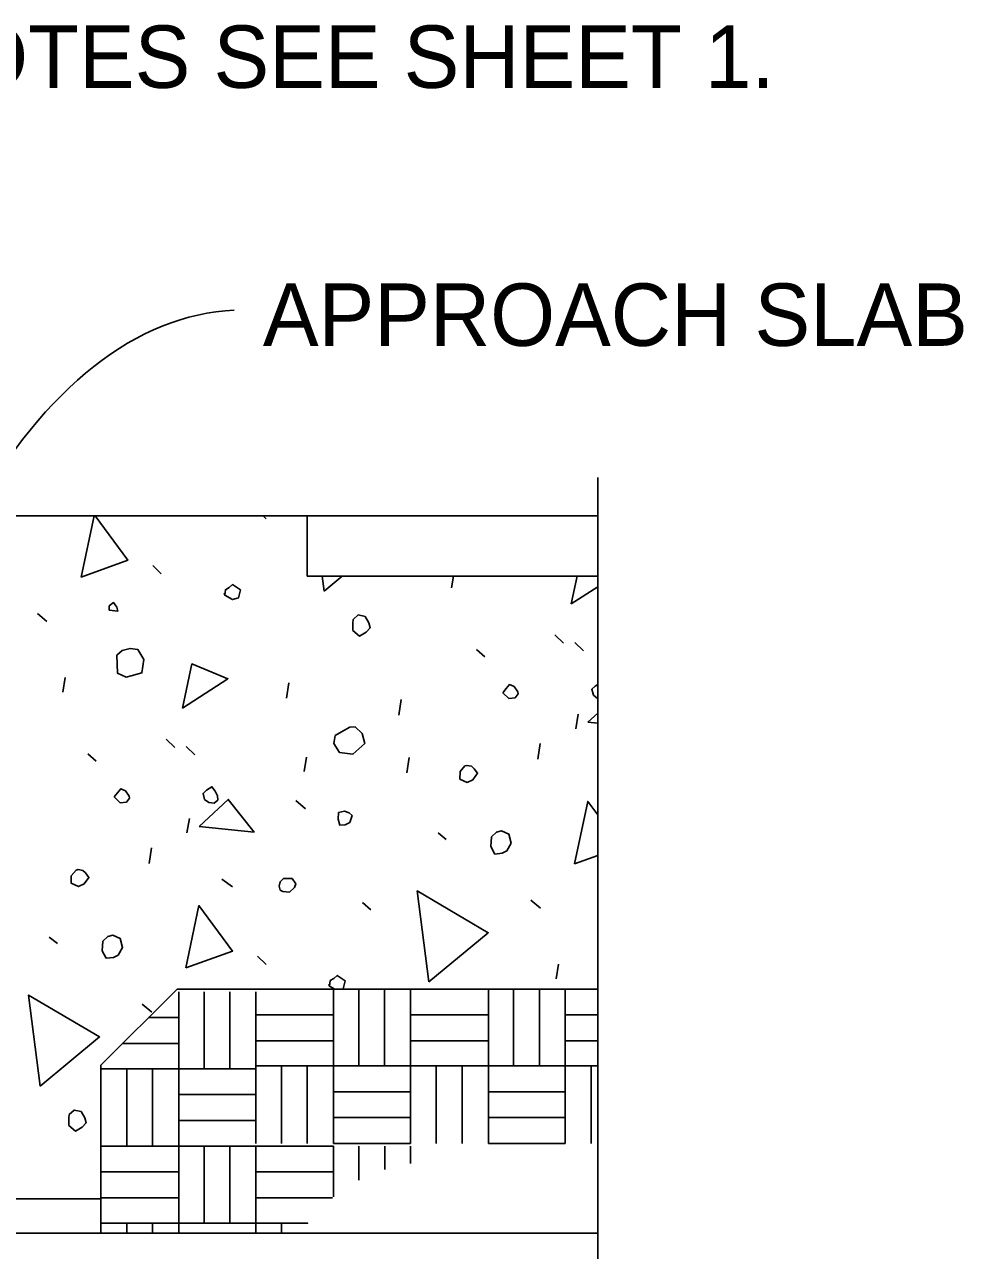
# Model space of a CAD drawing. Extents: x -1660015.2 to -1659984.9, y 2580594.2 to 2580616.7.
# Drawn here: x -1659987.657 to -1659985.382, y 2580602.277 to 2580605.246 of the extents above; entities that cross this region are included whole.
import ezdxf

# ---------------------------------------------------------------- set-up
doc = ezdxf.new("R2010")
doc.units = 0
for name, color, linetype in [('Default', 7, 'Continuous'), ('Miscellaneous', 7, 'Continuous'), ('Miscellaneous3', 7, 'Continuous'), ('PlotBorder_dp', 7, 'Continuous'), ('SheetLines_dp', 7, 'Continuous')]:
    doc.layers.add(name, color=color, linetype=linetype)

msp = doc.modelspace()

# ---------------------------------------------------------------- linework, layer by layer
at = {"layer": 'Default'}
msp.add_line((-1659986.2685, 2580602.3187), (-1659989.3273, 2580602.3187), dxfattribs=at)
at = {"layer": 'Miscellaneous'}
for p, q in [((-1659987.0793, 2580604.056), (-1659987.0714, 2580604.049)), ((-1659986.2685, 2580604.056), (-1659986.972, 2580604.056)), ((-1659987.3466, 2580603.9364), (-1659987.3257, 2580603.9161)), ((-1659986.6228, 2580603.8819), (-1659986.618, 2580603.9102)), ((-1659987.626, 2580603.8201), (-1659987.6027, 2580603.8005)), ((-1659986.3723, 2580603.7678), (-1659986.3513, 2580603.7476)), ((-1659986.5621, 2580603.7325), (-1659986.5418, 2580603.7146)), ((-1659986.3235, 2580603.7498), (-1659986.3025, 2580603.7296)), ((-1659987.5646, 2580603.6295), (-1659987.5585, 2580603.6648)), ((-1659987.0222, 2580603.6144), (-1659987.0168, 2580603.6521)), ((-1659986.7499, 2580603.5735), (-1659986.7444, 2580603.6112)), ((-1659986.3218, 2580603.5407), (-1659986.3157, 2580603.5759)), ((-1659987.3141, 2580603.5155), (-1659987.2931, 2580603.4952)), ((-1659987.2653, 2580603.4975), (-1659987.2443, 2580603.4772)), ((-1659986.4133, 2580603.4669), (-1659986.4079, 2580603.5046)), ((-1659987.5039, 2580603.4801), (-1659987.4836, 2580603.4623)), ((-1659986.9798, 2580603.4368), (-1659986.9737, 2580603.4721)), ((-1659986.7305, 2580603.4337), (-1659986.7251, 2580603.4714)), ((-1659986.9999, 2580603.3667), (-1659986.9765, 2580603.3471)), ((-1659987.2636, 2580603.2883), (-1659987.2575, 2580603.3236)), ((-1659986.6553, 2580603.2882), (-1659986.6356, 2580603.2728)), ((-1659987.3551, 2580603.2146), (-1659987.3497, 2580603.2523)), ((-1659987.1792, 2580603.1763), (-1659987.1534, 2580603.1574)), ((-1659986.838, 2580603.1202), (-1659986.8177, 2580603.1024)), ((-1659986.4306, 2580603.1258), (-1659986.4073, 2580603.1062)), ((-1659987.5971, 2580603.0359), (-1659987.5774, 2580603.0204)), ((-1659987.093, 2580602.9898), (-1659987.072, 2580602.9695)), ((-1659986.3692, 2580602.9352), (-1659986.3631, 2580602.9705)), ((-1659987.2832, 2580602.5297), (-1659987.2832, 2580602.9035)), ((-1659987.2219, 2580602.7172), (-1659987.2219, 2580602.9035)), ((-1659987.1594, 2580602.7172), (-1659987.1594, 2580602.9035)), ((-1659987.0971, 2580602.9101), (-1659986.9083, 2580602.9101)), ((-1659987.0969, 2580602.7172), (-1659987.0969, 2580602.9035)), ((-1659986.9083, 2580602.5364), (-1659986.9083, 2580602.9101)), ((-1659986.8471, 2580602.7239), (-1659986.8471, 2580602.9101)), ((-1659986.7846, 2580602.7239), (-1659986.7846, 2580602.9101)), ((-1659986.7221, 2580602.9101), (-1659986.5333, 2580602.9101)), ((-1659986.7221, 2580602.7239), (-1659986.7221, 2580602.9101)), ((-1659986.5333, 2580602.5364), (-1659986.5333, 2580602.9101)), ((-1659986.4721, 2580602.7239), (-1659986.4721, 2580602.9101)), ((-1659986.4096, 2580602.7239), (-1659986.4096, 2580602.9101)), ((-1659986.3471, 2580602.7239), (-1659986.3471, 2580602.9101)), ((-1659987.3724, 2580602.8735), (-1659987.349, 2580602.8539)), ((-1659987.3564, 2580602.841), (-1659987.2832, 2580602.841)), ((-1659987.0971, 2580602.8476), (-1659986.9083, 2580602.8476)), ((-1659986.7221, 2580602.8476), (-1659986.5333, 2580602.8476)), ((-1659986.3471, 2580602.8477), (-1659986.2685, 2580602.8477)), ((-1659987.0971, 2580602.7851), (-1659986.9083, 2580602.7851)), ((-1659986.7221, 2580602.7851), (-1659986.5333, 2580602.7851)), ((-1659986.3471, 2580602.7852), (-1659986.2685, 2580602.7852)), ((-1659987.4189, 2580602.7785), (-1659987.2832, 2580602.7785)), ((-1659987.0971, 2580602.7239), (-1659986.7221, 2580602.7239)), ((-1659987.0971, 2580602.7239), (-1659987.0971, 2580602.5364)), ((-1659987.0346, 2580602.7239), (-1659987.0346, 2580602.5364)), ((-1659986.9721, 2580602.7239), (-1659986.9721, 2580602.5364)), ((-1659986.7221, 2580602.7239), (-1659986.3471, 2580602.7239)), ((-1659986.7221, 2580602.7239), (-1659986.7221, 2580602.5364)), ((-1659986.6596, 2580602.7239), (-1659986.6596, 2580602.5364)), ((-1659986.5971, 2580602.7239), (-1659986.5971, 2580602.5364)), ((-1659986.3471, 2580602.7239), (-1659986.2685, 2580602.7239)), ((-1659986.3471, 2580602.7239), (-1659986.3471, 2580602.5364)), ((-1659986.2846, 2580602.7239), (-1659986.2846, 2580602.5364)), ((-1659987.4719, 2580602.7172), (-1659987.0969, 2580602.7172)), ((-1659987.4094, 2580602.7172), (-1659987.4094, 2580602.5297)), ((-1659987.3469, 2580602.7172), (-1659987.3469, 2580602.5297)), ((-1659987.2832, 2580602.6547), (-1659987.0969, 2580602.6547)), ((-1659986.9083, 2580602.6614), (-1659986.7221, 2580602.6614)), ((-1659986.5333, 2580602.6614), (-1659986.3471, 2580602.6614)), ((-1659987.2832, 2580602.5922), (-1659987.0969, 2580602.5922)), ((-1659986.9083, 2580602.5989), (-1659986.7221, 2580602.5989)), ((-1659986.5333, 2580602.5989), (-1659986.3471, 2580602.5989)), ((-1659987.4719, 2580602.5297), (-1659987.2832, 2580602.5297)), ((-1659987.2832, 2580602.3187), (-1659987.2832, 2580602.5298)), ((-1659987.2832, 2580602.5297), (-1659987.0969, 2580602.5297)), ((-1659987.2219, 2580602.3435), (-1659987.2219, 2580602.5297)), ((-1659987.1594, 2580602.3435), (-1659987.1594, 2580602.5297)), ((-1659987.0969, 2580602.5297), (-1659986.9082, 2580602.5297)), ((-1659987.0969, 2580602.3435), (-1659987.0969, 2580602.5297)), ((-1659986.9083, 2580602.5364), (-1659986.7221, 2580602.5364)), ((-1659986.9082, 2580602.4069), (-1659986.9082, 2580602.5298)), ((-1659986.8469, 2580602.447), (-1659986.8469, 2580602.5298)), ((-1659986.7844, 2580602.4735), (-1659986.7844, 2580602.5298)), ((-1659986.7219, 2580602.4875), (-1659986.7219, 2580602.5298)), ((-1659986.5333, 2580602.5364), (-1659986.3471, 2580602.5364)), ((-1659987.4719, 2580602.4672), (-1659987.2832, 2580602.4672)), ((-1659987.0969, 2580602.4672), (-1659986.9082, 2580602.4672)), ((-1659987.472, 2580602.402), (-1659988.972, 2580602.402)), ((-1659987.4719, 2580602.4047), (-1659987.2832, 2580602.4047)), ((-1659987.0969, 2580602.4048), (-1659986.9108, 2580602.4048)), ((-1659987.4719, 2580602.3435), (-1659987.0969, 2580602.3435)), ((-1659987.4094, 2580602.3435), (-1659987.4094, 2580602.3187)), ((-1659987.3469, 2580602.3435), (-1659987.3469, 2580602.3187)), ((-1659987.0969, 2580602.3435), (-1659986.9711, 2580602.3435)), ((-1659987.0969, 2580602.3435), (-1659987.0969, 2580602.3187)), ((-1659987.0344, 2580602.3435), (-1659987.0344, 2580602.3187)), ((-1659986.9719, 2580602.3435), (-1659986.9719, 2580602.3425))]:
    msp.add_line(p, q, dxfattribs=at)
for points in [[(-1659987.5202, 2580603.908), (-1659987.4888, 2580604.056)], [(-1659987.486, 2580604.056), (-1659987.4069, 2580603.9487), (-1659987.5202, 2580603.908)], [(-1659986.9314, 2580603.8742), (-1659986.9359, 2580603.9102)], [(-1659986.8878, 2580603.9102), (-1659986.9314, 2580603.8742)], [(-1659986.3329, 2580603.8431), (-1659986.3185, 2580603.9102)], [(-1659987.172, 2580603.8641), (-1659987.1536, 2580603.8535), (-1659987.1391, 2580603.8574), (-1659987.134, 2580603.8769), (-1659987.153, 2580603.8899), (-1659987.1614, 2580603.8825), (-1659987.1704, 2580603.8775), (-1659987.172, 2580603.8641), (-1659987.1733, 2580603.869)], [(-1659986.2685, 2580603.8845), (-1659986.3329, 2580603.8431)], [(-1659987.4521, 2580603.8279), (-1659987.4309, 2580603.8258), (-1659987.4335, 2580603.8355), (-1659987.4415, 2580603.8463), (-1659987.4523, 2580603.8382), (-1659987.4521, 2580603.8279)], [(-1659986.8616, 2580603.7972), (-1659986.8619, 2580603.779), (-1659986.8453, 2580603.7653), (-1659986.8297, 2580603.7747), (-1659986.8195, 2580603.7852), (-1659986.8228, 2580603.7972), (-1659986.8321, 2580603.8128), (-1659986.8485, 2580603.8162), (-1659986.8611, 2580603.8051), (-1659986.8616, 2580603.7972)], [(-1659987.4333, 2580603.719), (-1659987.432, 2580603.6754), (-1659987.4112, 2580603.6654), (-1659987.3991, 2580603.6687), (-1659987.3726, 2580603.6758), (-1659987.3682, 2580603.708), (-1659987.3826, 2580603.7326), (-1659987.4015, 2580603.7353), (-1659987.4208, 2580603.7302), (-1659987.4333, 2580603.719)], [(-1659987.2747, 2580603.5907), (-1659987.2516, 2580603.6978), (-1659987.1643, 2580603.6617), (-1659987.2747, 2580603.5907)], [(-1659986.4979, 2580603.628), (-1659986.4837, 2580603.6137), (-1659986.4686, 2580603.6152), (-1659986.4609, 2580603.625), (-1659986.4621, 2580603.6299), (-1659986.4709, 2580603.6431), (-1659986.4825, 2580603.6477), (-1659986.4902, 2580603.6379), (-1659986.4979, 2580603.628)], [(-1659986.2685, 2580603.6479), (-1659986.2744, 2580603.6439), (-1659986.2828, 2580603.6365), (-1659986.2789, 2580603.622)], [(-1659986.2789, 2580603.622), (-1659986.269, 2580603.6143), (-1659986.2685, 2580603.6142)], [(-1659986.2923, 2580603.5563), (-1659986.2685, 2580603.5785)], [(-1659986.2685, 2580603.5539), (-1659986.2923, 2580603.5563)], [(-1659986.9076, 2580603.5053), (-1659986.8939, 2580603.4831), (-1659986.8617, 2580603.4788), (-1659986.8324, 2580603.5048), (-1659986.8389, 2580603.5289), (-1659986.8561, 2580603.545), (-1659986.8688, 2580603.5442), (-1659986.8893, 2580603.5335), (-1659986.9049, 2580603.5242), (-1659986.9076, 2580603.5053)], [(-1659986.602, 2580603.4371), (-1659986.6023, 2580603.4189), (-1659986.5846, 2580603.4107), (-1659986.5708, 2580603.417), (-1659986.5595, 2580603.433), (-1659986.5676, 2580603.4437), (-1659986.5743, 2580603.4497), (-1659986.5853, 2580603.4519), (-1659986.5901, 2580603.4506), (-1659986.602, 2580603.4371)], [(-1659987.4397, 2580603.3757), (-1659987.4255, 2580603.3614), (-1659987.4103, 2580603.3629), (-1659987.4026, 2580603.3727), (-1659987.4039, 2580603.3775), (-1659987.4126, 2580603.3907), (-1659987.4242, 2580603.3954), (-1659987.432, 2580603.3855), (-1659987.4397, 2580603.3757)], [(-1659987.2207, 2580603.3697), (-1659987.2108, 2580603.362), (-1659987.1975, 2580603.3604), (-1659987.1891, 2580603.3678), (-1659987.1893, 2580603.3781), (-1659987.1949, 2580603.3895), (-1659987.203, 2580603.4003), (-1659987.2162, 2580603.3916), (-1659987.2245, 2580603.3842), (-1659987.2207, 2580603.3697)], [(-1659987.2341, 2580603.304), (-1659987.1636, 2580603.3694), (-1659987.1011, 2580603.2904), (-1659987.2341, 2580603.304)], [(-1659986.3248, 2580603.2137), (-1659986.2927, 2580603.3647), (-1659986.2685, 2580603.3318)], [(-1659986.8972, 2580603.3218), (-1659986.8933, 2580603.3073), (-1659986.8806, 2580603.3081), (-1659986.8692, 2580603.3137), (-1659986.8634, 2580603.3308), (-1659986.8702, 2580603.3368), (-1659986.8818, 2580603.3414), (-1659986.8963, 2580603.3375), (-1659986.8972, 2580603.3218)], [(-1659986.526, 2580603.2789), (-1659986.5274, 2580603.2552), (-1659986.5174, 2580603.2372), (-1659986.4998, 2580603.2393), (-1659986.4884, 2580603.2449), (-1659986.4778, 2580603.2633), (-1659986.4836, 2580603.2851), (-1659986.5014, 2580603.2932), (-1659986.5134, 2580603.29), (-1659986.526, 2580603.2789)], [(-1659986.2685, 2580603.234), (-1659986.3248, 2580603.2137)], [(-1659987.5438, 2580603.1847), (-1659987.5441, 2580603.1665), (-1659987.5264, 2580603.1584), (-1659987.5125, 2580603.1647), (-1659987.5013, 2580603.1806), (-1659987.5093, 2580603.1914), (-1659987.5161, 2580603.1973), (-1659987.5271, 2580603.1996), (-1659987.5319, 2580603.1983), (-1659987.5438, 2580603.1847)], [(-1659987.0374, 2580603.1496), (-1659987.0313, 2580603.1461), (-1659987.0155, 2580603.1451), (-1659987.003, 2580603.1562), (-1659987.0001, 2580603.1648), (-1659987.0088, 2580603.178), (-1659987.0294, 2580603.1776), (-1659987.0378, 2580603.1702), (-1659987.04, 2580603.1593), (-1659987.0374, 2580603.1496)], [(-1659986.6777, 2580602.9276), (-1659986.7057, 2580603.1479), (-1659986.5336, 2580603.0465), (-1659986.6777, 2580602.9276)], [(-1659987.2665, 2580602.9614), (-1659987.2345, 2580603.1123), (-1659987.1532, 2580603.0021), (-1659987.2665, 2580602.9614)], [(-1659987.4678, 2580603.0265), (-1659987.4692, 2580603.0029), (-1659987.4592, 2580602.9848), (-1659987.4416, 2580602.9869), (-1659987.4302, 2580602.9926), (-1659987.4196, 2580603.011), (-1659987.4254, 2580603.0327), (-1659987.4431, 2580603.0409), (-1659987.4552, 2580603.0377), (-1659987.4678, 2580603.0265)], [(-1659986.8878, 2580602.9102), (-1659986.8855, 2580602.9108), (-1659986.8803, 2580602.9303), (-1659986.8994, 2580602.9433), (-1659986.9077, 2580602.9359), (-1659986.9167, 2580602.9309), (-1659986.9183, 2580602.9175), (-1659986.9196, 2580602.9224)], [(-1659986.9183, 2580602.9175), (-1659986.9056, 2580602.9102)], [(-1659987.6195, 2580602.6753), (-1659987.6475, 2580602.8956), (-1659987.4754, 2580602.7941), (-1659987.6195, 2580602.6753)], [(-1659987.5497, 2580602.5982), (-1659987.55, 2580602.58), (-1659987.5334, 2580602.5664), (-1659987.5178, 2580602.5757), (-1659987.5077, 2580602.5862), (-1659987.5109, 2580602.5983), (-1659987.5202, 2580602.6139), (-1659987.5367, 2580602.6172), (-1659987.5492, 2580602.6061), (-1659987.5497, 2580602.5982)]]:
    msp.add_lwpolyline(points, dxfattribs=at)
at = {"layer": 'Miscellaneous3'}
for p, q in [((-1659986.972, 2580604.056), (-1659988.972, 2580604.056)), ((-1659986.972, 2580604.056), (-1659986.972, 2580603.9102)), ((-1659986.2685, 2580603.9102), (-1659986.972, 2580603.9102)), ((-1659987.472, 2580602.7255), (-1659987.2873, 2580602.9102)), ((-1659986.2685, 2580602.9102), (-1659987.2873, 2580602.9102)), ((-1659987.472, 2580602.3187), (-1659987.472, 2580602.7255))]:
    msp.add_line(p, q, dxfattribs=at)
at = {"layer": 'SheetLines_dp'}
msp.add_lwpolyline([(-1659986.2685, 2580601.863), (-1659986.2685, 2580604.1496)], dxfattribs=at)
msp.add_ellipse((-1659987.0381, 2580602.1871), major_axis=(0.1111, -2.3674), ratio=0.464296, start_param=3.141604, end_param=3.781059, dxfattribs=at)

# ---------------------------------------------------------------- texts
at = {"layer": 'PlotBorder_dp'}
msp.add_text('APPROACH SLAB', height=0.1512, dxfattribs=at).set_placement((-1659987.0795, 2580604.468))
at = {"layer": 'SheetLines_dp'}
msp.add_text('1.  FOR BOX GIRDER MAINTENANCE LIGHTING NOTES SEE SHEET 1.', height=0.1512, dxfattribs=at).set_placement((-1659992.5804, 2580605.0929))

doc.saveas('drawing.dxf')
